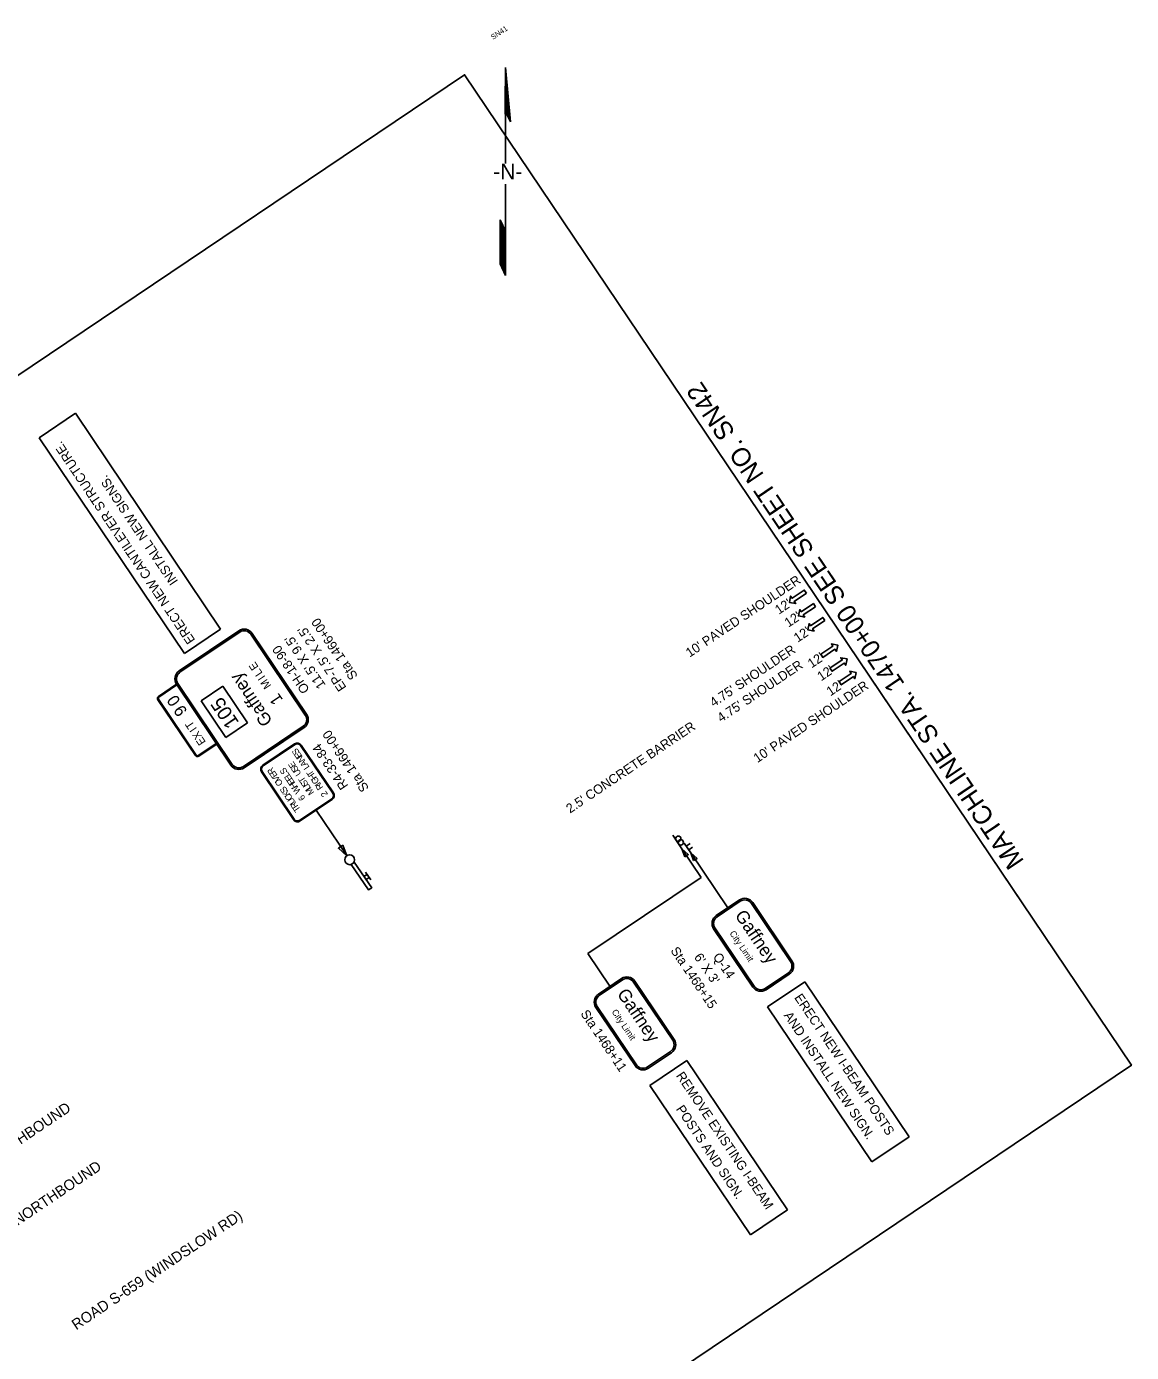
# Model space of a CAD drawing. Extents: x 1793197 to 1794941, y 1185753 to 1187457.
# Drawn here: x 1794113 to 1794941, y 1186463 to 1187457 of the extents above; entities that cross this region are included whole.
import ezdxf

# ---------------------------------------------------------------- set-up
doc = ezdxf.new("R2010")
doc.units = 0
for name, color, linetype in [('RD_PD_Final_LnLine', 7, 'Continuous'), ('RD_PD_Final_TX', 7, 'Continuous'), ('RD_SHT_MatchLine', 7, 'Continuous'), ('RD_SHT_ShtClip', 7, 'Continuous'), ('RD_SHT_TX', 7, 'Continuous'), ('RD_Sketch1', 7, 'Continuous'), ('RD_TX_RoadID', 7, 'Continuous'), ('SN_P_Signs', 7, 'Continuous')]:
    doc.layers.add(name, color=color, linetype=linetype)

# ---------------------------------------------------------------- blocks, each defined once
blk = doc.blocks.new('NA5')
at = {"layer": 'RD_Sketch1'}
for p, q in [((26.81, 30.64), (47.48, 65.89)), ((47.48, 65.89), (26.84, 37.43)), ((27.18, 37.55), (14.47, 19.81)), ((28.07, 38.27), (26.81, 30.64)), ((14.47, 19.81), (5.46, 7.23)), ((-3.53, -5.33), (-18.54, -26.28)), ((-18.54, -26.28), (-43.3, -60.85)), ((-30.56, -36.2), (-22.3, -24.68)), ((-22.3, -24.68), (-24.05, -33.97)), ((-41.56, -51.56), (-30.56, -36.2)), ((-43.3, -60.85), (-41.56, -51.56))]:
    blk.add_line(p, q, dxfattribs=at)
for points in [[(27.37, 37.79), (47.42, 65.79)], [(27.6, 37.95), (46.9, 64.9)], [(27.82, 38.1), (46.37, 64)], [(27.97, 37.66), (44.28, 60.42)], [(28, 37.87), (44.8, 61.32)], [(28.04, 38.08), (45.32, 62.21)], [(28.05, 38.26), (45.85, 63.11)], [(27.14, 37.64), (39.24, 54.53)], [(27.59, 35.34), (38.51, 50.58)], [(27.62, 35.55), (39.03, 51.48)], [(27.66, 35.76), (39.56, 52.37)], [(27.69, 35.97), (40.08, 53.27)], [(27.73, 36.18), (40.6, 54.16)], [(27.76, 36.39), (41.13, 55.06)], [(27.8, 36.6), (41.65, 55.95)], [(27.83, 36.82), (42.18, 56.85)], [(27.86, 37.03), (42.7, 57.74)], [(27.9, 37.24), (43.23, 58.63)], [(27.93, 37.45), (43.75, 59.53)], [(26.91, 37.48), (29.9, 41.66)], [(27.17, 32.81), (32.21, 39.85)], [(27.2, 33.02), (32.74, 40.75)], [(27.24, 33.23), (33.26, 41.64)], [(27.27, 33.44), (33.79, 42.54)], [(27.31, 33.65), (34.31, 43.43)], [(27.34, 33.86), (34.84, 44.32)], [(27.38, 34.07), (35.36, 45.22)], [(27.41, 34.28), (35.88, 46.11)], [(27.45, 34.5), (36.41, 47.01)], [(27.48, 34.71), (36.93, 47.9)], [(27.52, 34.92), (37.46, 48.8)], [(27.55, 35.13), (37.98, 49.69)], [(26.82, 30.7), (26.97, 30.91)], [(26.85, 30.91), (27.49, 31.8)], [(26.89, 31.12), (28.02, 32.7)], [(26.92, 31.33), (28.54, 33.59)], [(26.96, 31.54), (29.07, 34.49)], [(26.99, 31.75), (29.59, 35.38)], [(27.03, 31.96), (30.12, 36.27)], [(27.06, 32.18), (30.64, 37.17)], [(27.1, 32.39), (31.16, 38.06)], [(27.13, 32.6), (31.69, 38.96)], [(-42.5, -56.58), (-23.24, -29.69)], [(-42.46, -56.36), (-23.2, -29.47)], [(-42.42, -56.14), (-23.16, -29.25)], [(-42.38, -55.92), (-23.12, -29.03)], [(-42.34, -55.7), (-23.08, -28.81)], [(-42.3, -55.48), (-23.04, -28.59)], [(-42.25, -55.26), (-23, -28.37)], [(-42.21, -55.04), (-22.96, -28.15)], [(-42.17, -54.82), (-22.91, -27.93)], [(-42.13, -54.6), (-22.87, -27.71)], [(-42.09, -54.38), (-22.83, -27.49)], [(-42.05, -54.16), (-22.79, -27.27)], [(-42.01, -53.94), (-22.75, -27.05)], [(-41.97, -53.72), (-22.71, -26.83)], [(-41.93, -53.5), (-22.67, -26.62)], [(-41.88, -53.28), (-22.63, -26.4)], [(-41.84, -53.06), (-22.59, -26.18)], [(-41.8, -52.84), (-22.54, -25.96)], [(-41.76, -52.62), (-22.5, -25.74)], [(-41.72, -52.4), (-22.46, -25.52)], [(-41.68, -52.18), (-22.42, -25.3)], [(-41.64, -51.96), (-22.38, -25.08)], [(-41.6, -51.74), (-22.34, -24.86)], [(-43.28, -60.75), (-24.03, -33.87)], [(-43.24, -60.53), (-23.99, -33.65)], [(-43.2, -60.31), (-23.94, -33.43)], [(-43.16, -60.09), (-23.9, -33.21)], [(-43.12, -59.87), (-23.86, -32.99)], [(-43.08, -59.65), (-23.82, -32.77)], [(-43.04, -59.43), (-23.78, -32.55)], [(-43, -59.21), (-23.74, -32.33)], [(-42.95, -58.99), (-23.7, -32.11)], [(-42.91, -58.77), (-23.66, -31.89)], [(-42.87, -58.55), (-23.61, -31.67)], [(-42.83, -58.34), (-23.57, -31.45)], [(-42.79, -58.12), (-23.53, -31.23)], [(-42.75, -57.9), (-23.49, -31.01)], [(-42.71, -57.68), (-23.45, -30.79)], [(-42.67, -57.46), (-23.41, -30.57)], [(-42.63, -57.24), (-23.37, -30.35)], [(-42.58, -57.02), (-23.33, -30.13)], [(-42.54, -56.8), (-23.29, -29.91)]]:
    blk.add_lwpolyline(points, dxfattribs=at)
blk.add_text('-N-', height=11.811, rotation=324.3865, dxfattribs=at).set_placement((-8.85, 3.04))
blk = doc.blocks.new('SARRW2')
at = {"layer": 'RD_PD_Final_LnLine'}
blk.add_lwpolyline([(-12, 1.2), (-12, -1.2), (-2.83, -1.2), (-2.83, -2.83), (0, 0), (-2.83, 2.83), (-2.83, 1.2)], close=True, dxfattribs=at)

msp = doc.modelspace()

# ---------------------------------------------------------------- linework, layer by layer
at = {"layer": 'RD_SHT_MatchLine'}
msp.add_lwpolyline([(1794860.46, 1186798.22), (1794720.85, 1187005.61), (1794581.24, 1187213)], dxfattribs=at)
at = {"layer": 'RD_SHT_ShtClip'}
msp.add_lwpolyline([(1794333.99, 1186142.45), (1794275.36, 1186229.55), (1794941.43, 1186677.94), (1794441.63, 1187420.38), (1794441.63, 1187420.38), (1793197.31, 1186582.73), (1793755.74, 1185753.18)], close=True, dxfattribs=at)
at = {"layer": 'SN_P_Signs'}
for p, q in [((1794122.7, 1187148.35), (1794149.91, 1187166.67)), ((1794149.91, 1187166.67), (1794258.81, 1187004.9)), ((1794231.59, 1186986.58), (1794122.7, 1187148.35)), ((1794258.81, 1187004.9), (1794231.59, 1186986.58)), ((1794330.51, 1186869.16), (1794353.45, 1186835.09)), ((1794597.59, 1186850.41), (1794602.57, 1186842.91)), ((1794599.51, 1186847.63), (1794604.5, 1186840.14)), ((1794611.13, 1186837.31), (1794606.28, 1186844.52)), ((1794607.81, 1186842.24), (1794610.57, 1186844.1)), ((1794609.68, 1186839.47), (1794612.44, 1186841.33)), ((1794604.5, 1186840.14), (1794618.92, 1186818.71)), ((1794611.13, 1186837.31), (1794638.91, 1186796.04)), ((1794366.23, 1186819.36), (1794368.5, 1186820.93)), ((1794367.3, 1186822.65), (1794371.25, 1186816.92)), ((1794367.75, 1186817.15), (1794370.03, 1186818.73)), ((1794618.92, 1186818.71), (1794534.11, 1186761.62)), ((1794657.58, 1186799.92), (1794686.96, 1186756.29)), ((1794534.11, 1186761.62), (1794550.6, 1186737.13)), ((1794569.27, 1186741.02), (1794598.64, 1186697.39)), ((1794668.71, 1186721.68), (1794696.6, 1186740.45)), ((1794696.6, 1186740.45), (1794774.79, 1186624.29)), ((1794746.9, 1186605.52), (1794668.71, 1186721.68)), ((1794580.38, 1186662.76), (1794608.27, 1186681.53)), ((1794608.27, 1186681.53), (1794683.67, 1186569.53)), ((1794655.78, 1186550.76), (1794580.38, 1186662.76)), ((1794774.79, 1186624.29), (1794746.9, 1186605.52)), ((1794683.67, 1186569.53), (1794655.78, 1186550.76))]:
    msp.add_line(p, q, dxfattribs=at)
for points in [[(1794227.64, 1186973.49), (1794272.43, 1187003.64)], [(1794228.31, 1186972.49), (1794273.1, 1187002.65)], [(1794281.43, 1187001.02), (1794322.26, 1186940.37)], [(1794282.43, 1187001.69), (1794323.25, 1186941.04)], [(1794212.25, 1186954.45), (1794225.68, 1186963.49), (1794226.02, 1186963)], [(1794226.02, 1186963), (1794212.58, 1186953.95)], [(1794266.51, 1186902.84), (1794225.68, 1186963.49)], [(1794267.51, 1186903.51), (1794226.68, 1186964.16)], [(1794260.47, 1186962.1), (1794244.14, 1186951.11)], [(1794278.94, 1186934.67), (1794260.47, 1186962.1)], [(1794239.9, 1186910.14), (1794211.76, 1186951.95)], [(1794212.25, 1186952.28), (1794240.4, 1186910.47)], [(1794244.14, 1186951.11), (1794262.61, 1186923.67)], [(1794262.61, 1186923.67), (1794278.94, 1186934.67)], [(1794320.63, 1186932.04), (1794275.84, 1186901.88)], [(1794321.3, 1186931.05), (1794276.51, 1186900.89)], [(1794242.07, 1186910.15), (1794255.5, 1186919.2), (1794255.84, 1186918.7), (1794242.4, 1186909.65)], [(1794314.24, 1186918.97), (1794290.35, 1186902.88)], [(1794290.69, 1186902.39), (1794314.58, 1186918.47)], [(1794318.74, 1186917.66), (1794342.87, 1186881.82)], [(1794343.36, 1186882.15), (1794319.24, 1186917.99)], [(1794289.38, 1186897.89), (1794313.5, 1186862.05)], [(1794314, 1186862.39), (1794289.87, 1186898.22)], [(1794342.05, 1186877.66), (1794318.16, 1186861.57)], [(1794318.5, 1186861.08), (1794342.39, 1186877.16)], [(1794356.56, 1186828.45), (1794369.7, 1186809.41), (1794371.99, 1186810.99), (1794358.75, 1186830.19)], [(1794630.24, 1186790.2), (1794647.59, 1186801.88)], [(1794630.91, 1186789.2), (1794648.26, 1186800.88)], [(1794656.59, 1186799.25), (1794685.96, 1186755.62)], [(1794657.66, 1186736.57), (1794628.29, 1186780.2)], [(1794658.66, 1186737.24), (1794629.28, 1186780.87)], [(1794541.92, 1186731.29), (1794559.27, 1186742.97)], [(1794542.59, 1186730.3), (1794559.94, 1186741.98)], [(1794684.33, 1186747.29), (1794666.98, 1186735.61)], [(1794685, 1186746.3), (1794667.65, 1186734.62)], [(1794568.27, 1186740.35), (1794597.65, 1186696.72)], [(1794570.34, 1186678.34), (1794540.97, 1186721.97)], [(1794569.35, 1186677.67), (1794539.97, 1186721.3)], [(1794596.02, 1186688.39), (1794578.67, 1186676.71)], [(1794596.69, 1186687.39), (1794579.34, 1186675.71)]]:
    msp.add_lwpolyline(points, dxfattribs=at)
for points in [[(1794350.44, 1186842.98), (1794353.41, 1186835.06), (1794347.07, 1186840.65)], [(1794606.66, 1186834.17), (1794604.5, 1186840.14), (1794609.21, 1186835.89)], [(1794613.29, 1186831.34), (1794611.13, 1186837.31), (1794615.84, 1186833.06)]]:
    msp.add_lwpolyline(points, close=True, dxfattribs=at)
for centre, radius in [((1794601.78, 1186847.77), 2), ((1794603.7, 1186844.99), 2), ((1794355.52, 1186832.01), 3.71)]:
    msp.add_circle(centre, radius, dxfattribs=at)
for centre, radius, start, end in [((1794276.45, 1186997.67), 7.2, 33.94764, 123.94764), ((1794276.45, 1186997.67), 6, 33.94764, 123.94764), ((1794231.66, 1186967.51), 7.2, 123.94764, 213.94764), ((1794231.66, 1186967.51), 6, 123.94764, 213.94764), ((1794213.25, 1186952.95), 1.8, 123.94764, 213.94764), ((1794213.25, 1186952.95), 1.2, 123.94764, 213.94764), ((1794317.28, 1186937.02), 6, 303.94764, 33.94764), ((1794317.28, 1186937.02), 7.2, 303.94764, 33.94764), ((1794241.4, 1186911.14), 1.2, 213.94764, 303.94764), ((1794316.25, 1186915.98), 3.6, 33.94764, 123.94764), ((1794316.25, 1186915.98), 3, 33.94764, 123.94764), ((1794241.4, 1186911.14), 1.8, 213.94764, 303.94764), ((1794272.49, 1186906.86), 7.2, 213.94764, 303.94764), ((1794272.49, 1186906.86), 6, 213.94764, 303.94764), ((1794292.36, 1186899.9), 3.6, 123.94764, 213.94764), ((1794292.36, 1186899.9), 3, 123.94764, 213.94764), ((1794340.38, 1186880.14), 3, 303.94764, 33.94764), ((1794340.38, 1186880.14), 3.6, 303.94764, 33.94764), ((1794316.49, 1186864.06), 3.6, 213.94764, 303.94764), ((1794316.49, 1186864.06), 3, 213.94764, 303.94764), ((1794651.61, 1186795.9), 7.2, 33.94764, 123.94764), ((1794651.61, 1186795.9), 6, 33.94764, 123.94764), ((1794634.26, 1186784.22), 7.2, 123.94764, 213.94764), ((1794634.26, 1186784.22), 6, 123.94764, 213.94764), ((1794680.98, 1186752.27), 6, 303.94764, 33.94764), ((1794680.98, 1186752.27), 7.2, 303.94764, 33.94764), ((1794563.29, 1186737), 7.2, 33.94764, 123.94764), ((1794563.29, 1186737), 6, 33.94764, 123.94764), ((1794663.63, 1186740.59), 7.2, 213.94764, 303.94764), ((1794663.63, 1186740.59), 6, 213.94764, 303.94764), ((1794545.94, 1186725.32), 7.2, 123.94764, 213.94764), ((1794545.94, 1186725.32), 6, 123.94764, 213.94764), ((1794592.67, 1186693.37), 6, 303.94764, 33.94764), ((1794592.67, 1186693.37), 7.2, 303.94764, 33.94764), ((1794575.32, 1186681.69), 7.2, 213.94764, 303.94764), ((1794575.32, 1186681.69), 6, 213.94764, 303.94764)]:
    msp.add_arc(centre, radius, start, end, dxfattribs=at)

# ---------------------------------------------------------------- block references
at = {"layer": 'RD_PD_Final_LnLine', "xscale": 1.1999999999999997}
for p, yscale, rotation in [((1794685.04, 1187024.9), 1.2000000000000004, -146.05256015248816), ((1794691.87, 1187014.76), 1.2000000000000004, -146.05256015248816), ((1794698.86, 1187004.37), 1.2000000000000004, -146.05256015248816), ((1794721.24, 1186992.88), 1.2, 33.94743984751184), ((1794728.23, 1186982.49), 1.2, 33.94743984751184), ((1794735.06, 1186972.34), 1.2, 33.94743984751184)]:
    msp.add_blockref('SARRW2', p, dxfattribs=dict(at, yscale=yscale, rotation=rotation))
at = {"layer": 'RD_SHT_MatchLine', "rotation": 35.61349782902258}
msp.add_blockref('NA5', (1794472, 1187344.71), dxfattribs=at)

# ---------------------------------------------------------------- texts
at = {"layer": 'RD_PD_Final_TX'}
for s, p in [("10' PAVED SHOULDER", (1794610.35, 1186983.47)), ("12'", (1794677.16, 1187015.59)), ("12'", (1794684.33, 1187005.92)), ("12'", (1794691.27, 1186994.64)), ("4.75' SHOULDER", (1794628.38, 1186946.2)), ("4.75' SHOULDER", (1794633.89, 1186934.71)), ("12'", (1794701.7, 1186975.35)), ("12'", (1794708.87, 1186965.68)), ("10' PAVED SHOULDER", (1794661.09, 1186904.4)), ("12'", (1794715.81, 1186954.4)), ("2.5' CONCRETE BARRIER", (1794520.64, 1186866.55))]:
    msp.add_text(s, height=7, rotation=33.94744, dxfattribs=at).set_placement(p)
at = {"layer": 'RD_SHT_MatchLine'}
msp.add_text('MATCHLINE STA. 1470+00 SEE SHEET NO. SN42', height=14, rotation=123.94764, dxfattribs=at).set_placement((1794861.35, 1186830.92))
at = {"layer": 'RD_SHT_TX'}
msp.add_text('SN41', height=4, rotation=33.94764, dxfattribs=at).set_placement((1794462.94, 1187446.42))
at = {"layer": 'RD_TX_RoadID'}
for s, rotation, p in [('INTERSTATE 85 SOUTHBOUND', 33.94764, (1794014.18, 1186554.6)), ('INTERSTATE 85 NORTHBOUND', 33.94764, (1794036.64, 1186510.35)), ('ROAD S-659 (WINDSLOW RD)', 33.80657, (1794150.57, 1186479.22))]:
    msp.add_text(s, height=8, rotation=rotation, dxfattribs=at).set_placement(p)
at = {"layer": 'SN_P_Signs'}
for s, height, rotation, p in [('ERECT NEW CANTILEVER STRUCTURE.', 7, 123.94772, (1794239.97, 1186996.61)), ('INSTALL NEW SIGNS.', 7, 123.94772, (1794227.16, 1187040.72)), ('Sta 1466+00', 7, 123.94772, (1794361.9, 1186969.72)), ("EP-7.5' X 2.5'", 7, 123.94772, (1794353.32, 1186961.15)), ('OH-18-90', 7, 123.94772, (1794325.76, 1186959.47)), ("11.5' X 9.5'", 7, 123.94772, (1794337.78, 1186962.92)), ('E', 6, 123.94764, (1794287.48, 1186976.46)), ('Gaffney', 9.6, 123.94764, (1794298.11, 1186935.96)), ('L', 6, 123.94764, (1794290.5, 1186971.96)), ('I', 6, 123.94764, (1794292.51, 1186968.98)), ('M', 6, 123.94764, (1794296.9, 1186962.46)), ('0', 9, 123.94764, (1794229.09, 1186950.91)), ('105', 10.8, 123.94764, (1794272.94, 1186934.93)), ('1', 9, 123.94764, (1794305.82, 1186951.89)), ('9', 9, 123.94764, (1794234.18, 1186943.36)), ('T', 6, 123.94764, (1794239.56, 1186932.67)), ('I', 6, 123.94764, (1794241.23, 1186930.2)), ('X', 6, 123.94764, (1794245.03, 1186924.54)), ('E', 6, 123.94764, (1794247.91, 1186920.27)), ('Sta 1466+00', 7, 123.94772, (1794370.24, 1186885.69)), ('S', 4.8, 123.94764, (1794318.21, 1186912.55)), ('E', 4.8, 123.94764, (1794320, 1186909.88)), ('R4-33-84', 7, 123.94772, (1794354.74, 1186887.41)), ('R', 4.8, 123.94764, (1794299.86, 1186897.89)), ('S', 4.8, 123.94764, (1794309.19, 1186898.01)), ('E', 4.8, 123.94764, (1794315.44, 1186902.69)), ('S', 4.8, 123.94764, (1794317.47, 1186899.68)), ('N', 4.8, 123.94764, (1794322.03, 1186906.87)), ('A', 4.8, 123.94764, (1794324.16, 1186903.71)), ('L', 4.8, 123.94764, (1794325.65, 1186901.49)), ('E', 4.8, 123.94764, (1794301.66, 1186895.22)), ('V', 4.8, 123.94764, (1794303.74, 1186892.12)), ('O', 4.8, 123.94764, (1794305.75, 1186889.15)), ('L', 4.8, 123.94764, (1794310.98, 1186895.35)), ('E', 4.8, 123.94764, (1794312.77, 1186892.68)), ('E', 4.8, 123.94764, (1794314.56, 1186890.02)), ('U', 4.8, 123.94764, (1794319.5, 1186896.66)), ('T', 4.8, 123.94764, (1794322.85, 1186891.68)), ('S', 4.8, 123.94764, (1794324.77, 1186888.83)), ('T', 4.8, 123.94764, (1794329, 1186896.51)), ('H', 4.8, 123.94764, (1794330.92, 1186893.66)), ('G', 4.8, 123.94764, (1794332.95, 1186890.65)), ('S', 4.8, 123.94764, (1794309.22, 1186883.99)), ('K', 4.8, 123.94764, (1794311.14, 1186881.14)), ('C', 4.8, 123.94764, (1794313.06, 1186878.29)), ('H', 4.8, 123.94764, (1794316.59, 1186887)), ('W', 4.8, 123.94764, (1794319.06, 1186883.34)), ('U', 4.8, 123.94764, (1794326.8, 1186885.82)), ('M', 4.8, 123.94764, (1794329.1, 1186882.4)), ('I', 4.8, 123.94764, (1794333.89, 1186889.25)), ('R', 4.8, 123.94764, (1794335.92, 1186886.23)), ('2', 4.8, 123.94764, (1794339.4, 1186881.07)), ('U', 4.8, 123.94764, (1794315.09, 1186875.27)), ('R', 4.8, 123.94764, (1794317.12, 1186872.25)), ('T', 4.8, 123.94764, (1794318.91, 1186869.59)), ('6', 4.8, 123.94764, (1794322.53, 1186878.18)), ('Gaffney', 9.6, 303.94764, (1794643.83, 1186790.36)), ('City Limit', 4.8, 303.94764, (1794639.94, 1186776.87)), ('Sta 1468+15', 7, 303.94772, (1794595.67, 1186763.88)), ("6' X 3'", 7, 303.94772, (1794613.27, 1186759.05)), ('Q-14', 7, 303.94772, (1794627.42, 1186759.34)), ('Gaffney', 9.6, 303.94764, (1794555.51, 1186731.46)), ('ERECT NEW I-BEAM POSTS', 6.9998, 303.94772, (1794688.43, 1186728.65)), ('Sta 1468+11', 7, 303.94772, (1794528.21, 1186716.63)), ('City Limit', 4.8, 303.94764, (1794551.62, 1186717.97)), ('AND INSTALL NEW SIGN.', 6.9998, 303.94772, (1794680.56, 1186715.28)), ('REMOVE EXISTING I-BEAM', 6.9998, 303.94772, (1794599.83, 1186670.14)), ('POSTS AND SIGN.', 6.9998, 303.94772, (1794599.79, 1186645.14))]:
    msp.add_text(s, height=height, rotation=rotation, dxfattribs=at).set_placement(p)

doc.saveas('drawing.dxf')
